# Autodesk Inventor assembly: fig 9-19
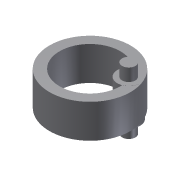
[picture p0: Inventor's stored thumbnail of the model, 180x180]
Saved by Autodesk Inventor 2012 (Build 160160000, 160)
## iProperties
Shininess: 64.0
Length Units: 11269
Angle Units: 11279
Time Units: 11290
Mass Units: 11283
Length Display Precision: 3
Angle Display Precision: 2
Created: 2002-01
Part Number: fig 9-19
Document SubType Name: Assembly
Designer: ***
Density: 0.0
Volumn: 0.0
Area: 0.0
PropertySet Name: Model Information
Control State: 0
Master: False
Checked Out: False
Author: ***
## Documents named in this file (3)
- C:\Users\CadCim\Documents\SAILESH\inventor-2011-fact-prt\c09_inv_2011-prt\c09_inv_2012_prt\fig 9-19.iam
- C:\Users\CadCim\Documents\SAILESH\inventor-2011-fact-prt\c09_inv_2011-prt\c09_inv_2012_prt\Part8.ipt
- C:\Users\CadCim\Documents\SAILESH\inventor-2011-fact-prt\c09_inv_2011-prt\Part9.ipt
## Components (2 placed, 2 different names)
1. Part8:1 — Flush:1
2. Part9:1 — Flush:1
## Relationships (1: Flush 1)
- Flush:1: Part8:1 ↔ Part9:1
